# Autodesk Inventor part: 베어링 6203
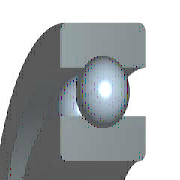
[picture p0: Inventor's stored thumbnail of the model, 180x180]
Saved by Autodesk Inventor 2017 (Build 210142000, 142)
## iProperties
IsCustomPart: 0
Created: 2009-02
Part Number: 베어링 6203
Material: 강철, 연강
Description: 깊은 그루브 볼 베어링
Document SubType Name: Modeling
Standard: KS B 2023
Standards Organization: KS
Language: ko-KR
Size Designation: 6203 - 17 x 40 x 12
Categories: <MemberInstance><Categories><Category DisplayName="샤프트 부품" InternalName="7f7aeb1f-a693-4053-b835-cee3144e0d98" Mnemonic="SHFT"><Category DisplayName="베어링" Inter
Density: 1 g/cm^3
Appearance: 밝은 황색
Author: pww
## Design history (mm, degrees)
sketch "스케치" dims "d0" = 5.98 (= -0.26 x WD + 0.26 x BD)
  geometry: L1 (3.01, 14.25)-(8.99, 14.25); L2 (6, 14.25)-(6, 11.26); L3 (6, 14.25)-(6, 17.24); L4 (3.778, 12.249)-(0, 12.249); L5 (0, 8.5)-(12, 8.5); L6 (3.778, 16.251)-(0, 16.251); L7 (0, 20)-(12, 20); L8 (12, 8.5)-(12, 12.249); L9 (8.222, 12.249)-(12, 12.249); L10 (8.222, 16.251)-(12, 16.251); L11 (12, 20)-(12, 16.251); L12 (-1.4, 0)-(8.4, 0) reference; L13 (0, -0.3)-(0, 5.3) reference
  constraints: 22 end point, 4 point on line, 2 collinear, 2 perpendicular, 2 symmetric about line, 1 midpoint, 1 parallel, 14 other
  dimensions: "d9" = 17 diameter of L5 L12 (= WD); "d11" = 40 diameter of L7 L12 (= BD); "d12" = 12 distance between parallel lines of L8 L13 (= KB); "d13" = 24.498 diameter of L9 L12 (= 0.326 x BD + 0.674 x WD)
revolve "본체" stored, may be unused: angle "d6" = 90 deg
revolve "볼" stored, may be unused: angle "d7" = 90 deg
pattern_circular "IDS_ARRAYBALL[SIMPL:T]" dims angle "d3" = 360 deg
body "Solid1"
fillet "모깎기1" dims "d1" = 0.6 (= KRS)
other parameters: "WD" = 17 [user parameter; used in 5 equation terms], "BD" = 40 [user parameter; used in 5 equation terms], "KB" = 12 [user parameter; used in 1 equation term], "KRS" = 0.6 [user parameter; used in 1 equation term], "d4" = 0, "d5" = 0, "d8" = 0, "d14" = 0, "d15" = 0, "BBA" = 0 [user parameter], "BC0" = 4750000 [user parameter], "BC" = 9560000 [user parameter], "WR" = 8.5 (= 0.5 x WD) [user parameter]
